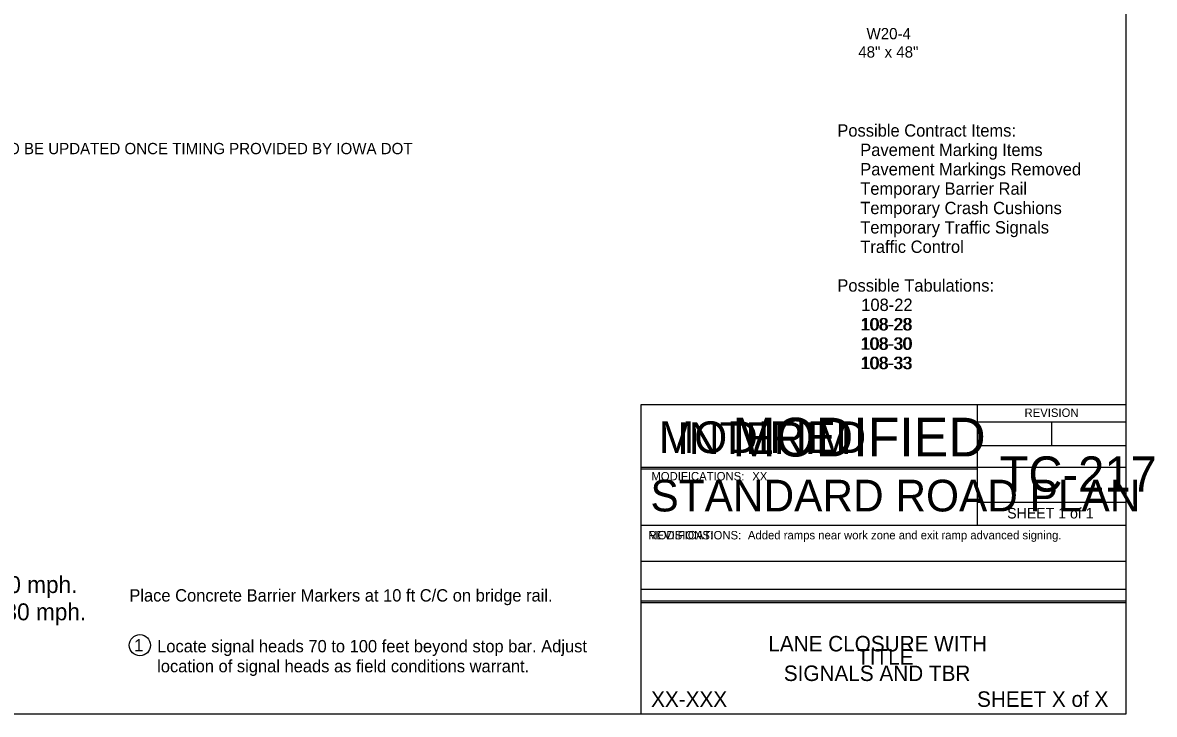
# Model space of a CAD drawing. Extents: x -2134934 to -2122394, y -2139046 to -2137036.
# Drawn here: x -2133366 to -2131759, y -2139046 to -2138064 of the extents above; entities that cross this region are included whole.
import ezdxf

# ---------------------------------------------------------------- set-up
doc = ezdxf.new("R2010")
doc.units = 0
for name, color, linetype in [('Barrier', 7, 'Continuous'), ('BridgeSuperStructureExisting', 7, 'Continuous'), ('Default', 7, 'Continuous'), ('Dimension', 7, 'Continuous'), ('dsnAlignmentCurveData', 7, 'Continuous'), ('dsnAlignmentTic', 7, 'Continuous'), ('dsnCellElements', 7, 'Continuous'), ('DsnShtOutsideBorder', 7, 'Continuous'), ('dsnStdLabel', 7, 'Continuous'), ('hwyPlanSheetShape', 7, 'Continuous')]:
    doc.layers.add(name, color=color, linetype=linetype)

msp = doc.modelspace()

# ---------------------------------------------------------------- linework, layer by layer
at = {"layer": 'BridgeSuperStructureExisting'}
msp.add_circle((-2133199.2, -2138947.8), 15, dxfattribs=at)
at = {"layer": 'Default'}
msp.add_lwpolyline([(-2134934.4, -2137035.9), (-2131799.4, -2137035.9), (-2131799.4, -2139045.9), (-2134934.4, -2139045.9)], close=True, dxfattribs=at)
at = {"layer": 'Dimension'}
for p, q in [((-2132010.4, -2138605.9), (-2132010.4, -2138697.3)), ((-2132010.4, -2138630.9), (-2131799.4, -2138630.9)), ((-2131904.9, -2138630.9), (-2131904.9, -2138664.1)), ((-2132010.4, -2138664.1), (-2131799.4, -2138664.1)), ((-2132487.5, -2138697.3), (-2132010.4, -2138697.3)), ((-2132010.4, -2138697.3), (-2132010.4, -2138777.3)), ((-2131799.4, -2138745.1), (-2132010.4, -2138745.1)), ((-2132487.5, -2138777.3), (-2131799.4, -2138777.3)), ((-2132487.5, -2138828.3), (-2131799.4, -2138828.3)), ((-2132487.5, -2138868.3), (-2131799.4, -2138868.3)), ((-2132487.5, -2138887.3), (-2131799.4, -2138887.3))]:
    msp.add_line(p, q, dxfattribs=at)
msp.add_lwpolyline([(-2132487.5, -2138605.9), (-2131799.4, -2138605.9), (-2131799.4, -2139045.9), (-2132487.5, -2139045.9)], close=True, dxfattribs=at)
at = {"layer": 'DsnShtOutsideBorder'}
for p, q in [((-2132487.5, -2138695), (-2131799.4, -2138695)), ((-2132487.5, -2138885), (-2131799.4, -2138885))]:
    msp.add_line(p, q, dxfattribs=at)
msp.add_lwpolyline([(-2132487.5, -2138605.9), (-2131799.4, -2138605.9), (-2131799.4, -2139045.9), (-2132487.5, -2139045.9)], close=True, dxfattribs=at)

# ---------------------------------------------------------------- texts
at = {"layer": 'Barrier'}
for s, p in [('W20-4', (-2132167.7, -2138087.7)), ('48" x 48"', (-2132179.4, -2138113.7))]:
    msp.add_text(s, height=16, dxfattribs=at).set_placement(p)
at = {"layer": 'BridgeSuperStructureExisting'}
for s, height, p in [('TO BE UPDATED ONCE TIMING PROVIDED BY IOWA DOT', 16, (-2133399.4, -2138250.8)), ('1', 17.5, (-2133207.3, -2138956.6)), ('Locate signal heads 70 to 100 feet beyond stop bar. Adjust ', 17.5, (-2133174.7, -2138957.9)), ('location of signal heads as field conditions warrant.', 17.5, (-2133174.7, -2138986.2))]:
    msp.add_text(s, height=height, dxfattribs=at).set_placement(p)
at = {"layer": 'Dimension'}
for s, height, p in [('REVISION', 12, (-2131943.4, -2138623.8)), ('TC-217', 50, (-2131978.7, -2138729.8)), ('STANDARD ROAD PLAN', 45.001, (-2132474.4, -2138757.9)), ('SHEET 1 of 1', 15, (-2131968, -2138767.9)), ('Added ramps near work zone and exit ramp advanced signing.', 12, (-2132336.1, -2138797.5)), ('LANE CLOSURE WITH', 22, (-2132307.1, -2138956.6)), ('SIGNALS AND TBR', 22, (-2132285.1, -2138998.6))]:
    msp.add_text(s, height=height, dxfattribs=at).set_placement(p)
at = {"layer": 'dsnAlignmentCurveData'}
msp.add_text('REVISIONS:', height=12, dxfattribs=at).set_placement((-2132477.5, -2138797.6))
at = {"layer": 'dsnAlignmentTic'}
for s, height, p in [('MODIFIED', 45, (-2132462.4, -2138675.1)), ('MODIFICATIONS:', 12, (-2132477.5, -2138797.6))]:
    msp.add_text(s, height=height, dxfattribs=at).set_placement(p)
at = {"layer": 'dsnCellElements'}
for s, p in [('Possible Contract Items:', (-2132209.1, -2138225.9)), ('     Pavement Marking Items', (-2132209.1, -2138253.4)), ('     Pavement Markings Removed', (-2132209.1, -2138280.9)), ('     Temporary Barrier Rail', (-2132209.1, -2138308.4)), ('     Temporary Crash Cushions', (-2132209.1, -2138335.9)), ('     Temporary Traffic Signals', (-2132209.1, -2138363.4)), ('     Traffic Control', (-2132209.1, -2138390.9)), ('Possible Tabulations:', (-2132209.1, -2138445.9)), ('108-22', (-2132175.2, -2138473.3)), ('108-22', (-2132175.2, -2138473.4)), ('     108-28', (-2132209.1, -2138500.9)), ('108-28', (-2132175.2, -2138500.9)), ('     108-30', (-2132209.1, -2138528.4)), ('108-30', (-2132175.2, -2138528.4)), ('     108-33', (-2132209.1, -2138555.9)), ('108-33', (-2132175.2, -2138555.9)), ('Place Concrete Barrier Markers at 10 ft C/C on bridge rail.', (-2133214.2, -2138885.8))]:
    msp.add_text(s, height=17.5, dxfattribs=at).set_placement(p)
at = {"layer": 'DsnShtOutsideBorder'}
for s, height, p in [('MODIFIED', 55, (-2132358.1, -2138679.9)), ('MODIFICATIONS:', 12, (-2132473.1, -2138713.9)), ('XX', 12, (-2132329.9, -2138713.9)), ('TITLE', 22, (-2132181.1, -2138975.4)), ('XX-XXX', 22, (-2132473.5, -2139035.3)), ('SHEET X of X', 22, (-2132010.8, -2139035.3))]:
    msp.add_text(s, height=height, dxfattribs=at).set_placement(p)
at = {"layer": 'dsnStdLabel'}
for s, p in [('*All Red clearance value based on an operating speed of 20 mph.', (-2134222.8, -2138873.7)), ('**All Red clearance value based on an operating speed of 30 mph.', (-2134222.8, -2138912.4))]:
    msp.add_text(s, height=24, dxfattribs=at).set_placement(p)
at = {"layer": 'hwyPlanSheetShape'}
msp.add_text('INTERIM', height=45, dxfattribs=at).set_placement((-2132436.5, -2138676.3))

doc.saveas('drawing.dxf')
